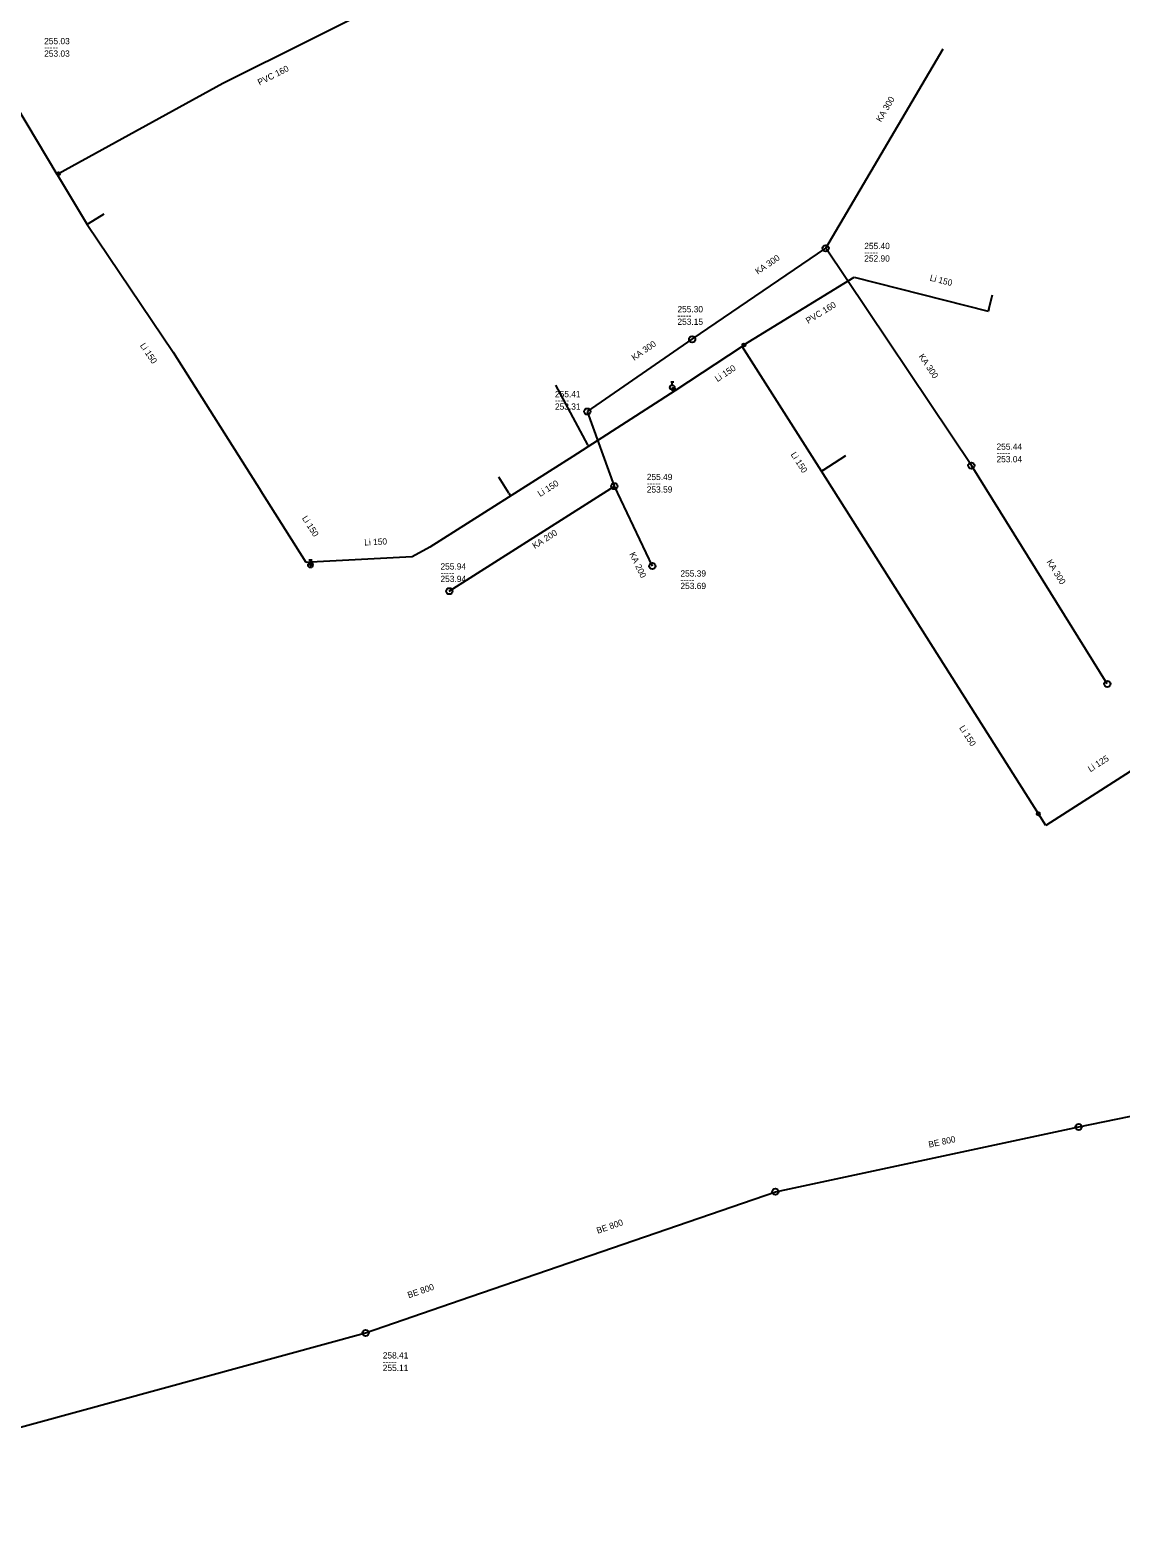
# Model space of a CAD drawing. Extents: x -647357 to -646700, y -1072205 to -1071664.
# Drawn here: x -646977 to -646802.6, y -1072204.7 to -1071963.6 of the extents above; entities that cross this region are included whole.
import ezdxf

# ---------------------------------------------------------------- set-up
doc = ezdxf.new("R2010")
doc.units = 0
for name, color, linetype in [('Level 19', 7, 'Continuous'), ('Level 20', 7, 'Continuous'), ('Level 21', 7, 'Continuous'), ('Level 24', 7, 'Continuous'), ('Level 26', 7, 'Continuous'), ('Level 40', 7, 'Continuous'), ('Level 41', 7, 'Continuous'), ('Level 44', 7, 'Continuous')]:
    doc.layers.add(name, color=color, linetype=linetype)

msp = doc.modelspace()

# ---------------------------------------------------------------- linework, layer by layer
at = {"layer": 'Level 19'}
for p, q in [((-646967.64, -1071994.57), (-646967.88, -1071994.73)), ((-646967.64, -1071994.57), (-646965.15, -1071993.02)), ((-646823.7, -1072008.27), (-646823.12, -1072005.94)), ((-646823.7, -1072008.27), (-646823.77, -1072008.54)), ((-646887.78, -1072029.95), (-646892.89, -1072020.37)), ((-646887.78, -1072029.95), (-646887.65, -1072030.15)), ((-646850.19, -1072033.96), (-646846.54, -1072031.63)), ((-646900.43, -1072037.66), (-646902.04, -1072035.12)), ((-646850.19, -1072033.96), (-646850.43, -1072034.12)), ((-646900.43, -1072037.66), (-646900.16, -1072038.1))]:
    msp.add_line(p, q, dxfattribs=at)
at = {"layer": 'Level 20'}
for p, q in [((-646946.17, -1071972.11), (-646907.17, -1071952.67)), ((-646972.64, -1071986.74), (-646985.48, -1071965.29)), ((-646972.43, -1071986.57), (-646946.17, -1071972.11)), ((-646972.43, -1071986.57), (-646972.64, -1071986.74)), ((-646972.64, -1071986.74), (-646967.88, -1071994.73)), ((-646967.88, -1071994.73), (-646954.11, -1072015.14)), ((-646862.83, -1072013.96), (-646845.22, -1072003.12)), ((-646845.22, -1072003.12), (-646823.77, -1072008.54)), ((-646863.14, -1072014.21), (-646873.91, -1072021.32)), ((-646863.14, -1072014.21), (-646862.83, -1072013.96)), ((-646850.43, -1072034.12), (-646863.14, -1072014.21)), ((-646954.11, -1072015.14), (-646940.07, -1072037.29)), ((-646873.91, -1072021.32), (-646890.18, -1072031.78)), ((-646874.06, -1072021.08), (-646874.3, -1072020.76)), ((-646873.91, -1072021.32), (-646874.06, -1072021.08)), ((-646890.18, -1072031.78), (-646913.08, -1072046.28)), ((-646815.76, -1072088.92), (-646850.43, -1072034.12)), ((-646932.83, -1072048.74), (-646940.07, -1072037.29)), ((-646915.89, -1072047.84), (-646932.08, -1072048.7)), ((-646913.08, -1072046.28), (-646915.89, -1072047.84)), ((-646932.08, -1072048.7), (-646932.83, -1072048.74)), ((-646932.15, -1072049.18), (-646932.08, -1072048.95)), ((-646932.08, -1072048.95), (-646932.08, -1072048.7)), ((-646795.86, -1072078.77), (-646814.55, -1072090.76)), ((-646814.55, -1072090.76), (-646815.76, -1072088.92))]:
    msp.add_line(p, q, dxfattribs=at)
at = {"layer": 'Level 21'}
for p, q in [((-646874.55, -1072019.885), (-646874.05, -1072019.885)), ((-646874.3, -1072020.385), (-646874.3, -1072019.885)), ((-646932.4, -1072048.305), (-646931.9, -1072048.305)), ((-646932.15, -1072048.805), (-646932.15, -1072048.305))]:
    msp.add_line(p, q, dxfattribs=at)
for centre in [(-646874.3, -1072020.76), (-646932.15, -1072049.18)]:
    msp.add_circle(centre, 0.375, dxfattribs=at)
at = {"layer": 'Level 26'}
for centre in [(-646972.43, -1071986.57), (-646862.83, -1072013.96), (-646874.06, -1072021.08), (-646932.08, -1072048.95), (-646815.76, -1072088.92)]:
    msp.add_circle(centre, 0.25, dxfattribs=at)
at = {"layer": 'Level 40'}
for p, q in [((-646849.76, -1071998.51), (-646830.99, -1071966.63)), ((-646871.12, -1072013.06), (-646849.76, -1071998.51)), ((-646826.47, -1072033.26), (-646849.76, -1071998.51)), ((-646887.87, -1072024.6), (-646871.12, -1072013.06)), ((-646883.55, -1072036.54), (-646887.87, -1072024.6)), ((-646804.74, -1072068.15), (-646826.47, -1072033.26)), ((-646909.96, -1072053.32), (-646883.55, -1072036.54)), ((-646877.47, -1072049.31), (-646883.55, -1072036.54)), ((-646809.3, -1072138.97), (-646760.91, -1072129.04)), ((-646857.81, -1072149.33), (-646809.3, -1072138.97)), ((-646908.21, -1072166.69), (-646857.81, -1072149.33)), ((-646923.34, -1072171.9), (-646908.21, -1072166.69)), ((-647043.27, -1072204.66), (-646923.34, -1072171.9))]:
    msp.add_line(p, q, dxfattribs=at)
at = {"layer": 'Level 41'}
for centre in [(-646849.76, -1071998.51), (-646871.12, -1072013.06), (-646887.87, -1072024.6), (-646826.47, -1072033.26), (-646883.55, -1072036.54), (-646877.47, -1072049.31), (-646909.96, -1072053.32), (-646804.74, -1072068.15), (-646809.3, -1072138.97), (-646857.81, -1072149.33), (-646923.34, -1072171.9)]:
    msp.add_circle(centre, 0.5, dxfattribs=at)

# ---------------------------------------------------------------- texts
at = {"layer": 'Level 24'}
for s, rotation, p in [('PVC 160', 26.494, (-646940.29, -1071972.5)), ('Li 150', 345.819, (-646833.19, -1072003.67)), ('PVC 160', 31.615, (-646852.56, -1072010.62)), ('Li 150', 304.006, (-646959.46, -1072014.06)), ('Li 150', 33.431, (-646867.07, -1072019.92)), ('Li 150', 302.553, (-646855.41, -1072031.47)), ('Li 150', 32.341, (-646895.43, -1072038.29)), ('Li 150', 302.306, (-646933.55, -1072041.66)), ('Li 150', 3.041, (-646923.52, -1072046.04)), ('Li 150', 302.553, (-646828.46, -1072075.17)), ('Li 125', 32.681, (-646807.44, -1072082.29))]:
    msp.add_text(s, height=1, rotation=rotation, dxfattribs=at).set_placement(p)
at = {"layer": 'Level 44'}
for s, p in [('255.03', (-646974.73, -1071965.89)), ('-----', (-646974.73, -1071966.89)), ('253.03', (-646974.73, -1071967.89)), ('-----', (-646843.6, -1071999.64)), ('255.40', (-646843.6, -1071998.64)), ('252.90', (-646843.6, -1072000.64)), ('-----', (-646873.47, -1072009.75)), ('255.30', (-646873.47, -1072008.75)), ('253.15', (-646873.47, -1072010.75)), ('255.41', (-646893.05, -1072022.32)), ('-----', (-646893.05, -1072023.32)), ('253.31', (-646893.05, -1072024.32)), ('255.44', (-646822.45, -1072030.72)), ('-----', (-646822.45, -1072031.72)), ('253.04', (-646822.45, -1072032.72)), ('255.49', (-646878.37, -1072035.57)), ('-----', (-646878.37, -1072036.57)), ('253.59', (-646878.37, -1072037.57)), ('-----', (-646911.36, -1072050.87)), ('255.94', (-646911.36, -1072049.87)), ('255.39', (-646872.99, -1072050.99)), ('253.94', (-646911.36, -1072051.87)), ('-----', (-646872.99, -1072051.99)), ('253.69', (-646872.99, -1072052.99)), ('258.41', (-646920.59, -1072175.99)), ('-----', (-646920.59, -1072176.99)), ('255.11', (-646920.59, -1072177.99))]:
    msp.add_text(s, height=1, dxfattribs=at).set_placement(p)
for s, rotation, p in [('KA 300', 59.512, (-646840.92, -1071978.41)), ('KA 300', 34.262, (-646860.62, -1072002.75)), ('KA 300', 34.565, (-646880.39, -1072016.52)), ('KA 300', 303.831, (-646834.95, -1072015.8)), ('KA 200', 32.43, (-646896.28, -1072046.6)), ('KA 200', 295.46, (-646881.18, -1072047.37)), ('KA 300', 301.915, (-646814.49, -1072048.65)), ('BE 800', 12.055, (-646833.22, -1072142.29)), ('BE 800', 19.006, (-646886.21, -1072156.06)), ('BE 800', 19.001, (-646916.43, -1072166.37))]:
    msp.add_text(s, height=1, rotation=rotation, dxfattribs=at).set_placement(p)

doc.saveas('drawing.dxf')
